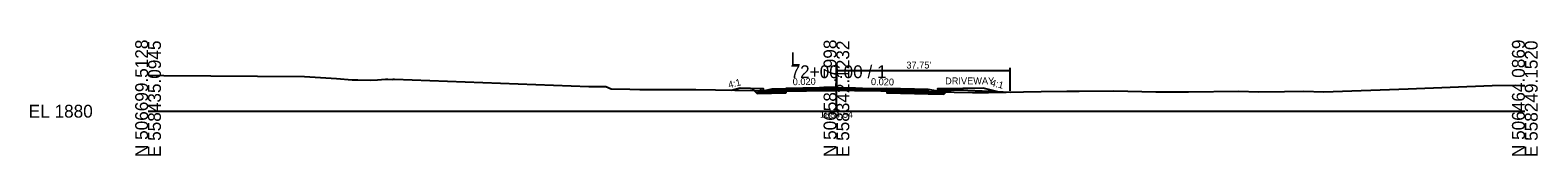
# Model space of a CAD drawing. Extents: x -26 to 4603, y -10 to 4703.
# Drawn here: x 2974.3 to 3302.8, y 835.3 to 860.4 of the extents above; entities that cross this region are included whole.
import ezdxf

# ---------------------------------------------------------------- set-up
doc = ezdxf.new("R2010")
doc.units = 0
for name, color, linetype in [('Default', 7, 'Continuous'), ('Exist Cross Section Cell', 7, 'Continuous'), ('Exist XS Ground Line', 7, 'Continuous'), ('Prop CMT Pvmt Course 1', 7, 'Continuous'), ('Prop CMT Pvmt Course 2', 7, 'Continuous'), ('Prop CMT Pvmt Course 3', 7, 'Continuous'), ('Prop CMT Pvmt Milling', 7, 'Continuous'), ('Prop CMT Shear Line', 7, 'Continuous'), ('Prop CMT Shld Paved Course 2', 7, 'Continuous'), ('Prop CMT Shld Paved Course 3', 7, 'Continuous'), ('Prop CMT Subgrade Earthwork', 7, 'Continuous'), ('Prop Conc Curb and Gutter', 7, 'Continuous'), ('Prop Corridor Mesh Bottom', 7, 'Continuous'), ('Prop XS Finish Grade', 7, 'Continuous'), ('Prop XS Label Text', 7, 'Continuous'), ('Prop XS SS Elevation Text', 7, 'Continuous'), ('Scratch_Level_0', 7, 'Continuous'), ('Scratch_Level_9', 7, 'Continuous')]:
    doc.layers.add(name, color=color, linetype=linetype)

msp = doc.modelspace()

# ---------------------------------------------------------------- linework, layer by layer
at = {"layer": 'Exist Cross Section Cell'}
for p, q in [((3150, 845), (3150, 855)), ((3000, 845), (3150, 845)), ((3150, 845), (3300, 845))]:
    msp.add_line(p, q, dxfattribs=at)
at = {"layer": 'Exist XS Ground Line'}
msp.add_lwpolyline([(3000, 852.83), (3003.45, 852.8), (3034.12, 852.55), (3041.03, 852.13), (3044.44, 851.81), (3045.7, 851.85), (3048.37, 851.75), (3049.97, 851.84), (3051.76, 851.95), (3052.24, 851.98), (3053.37, 851.9), (3053.42, 852), (3053.67, 851.99), (3096.07, 850.41), (3097.97, 850.38), (3099.73, 850.36), (3100.94, 849.86), (3104.97, 849.81), (3107.13, 849.75), (3113.36, 849.74), (3119.39, 849.76), (3132.18, 849.5), (3133.44, 849.47), (3134.15, 849.46), (3152.76, 849.55), (3153.2, 849.55), (3153.95, 849.54), (3154.03, 849.53), (3154.15, 849.53), (3155.68, 849.51), (3179.67, 849.07), (3183.14, 849.05), (3194.59, 849.27), (3200.24, 849.36), (3202.91, 849.37), (3210.41, 849.47), (3219.59, 849.23), (3226.74, 849.23), (3237.66, 849.34), (3241.98, 849.25), (3247.65, 849.3), (3251.77, 849.33), (3256.23, 849.24), (3274.58, 849.91), (3292.9, 850.61), (3298.03, 850.66), (3300, 850.56)], dxfattribs=at)
at = {"layer": 'Prop CMT Pvmt Course 1'}
for points in [[(3136, 849.87), (3139, 849.93), (3139, 849.68), (3139, 849.68), (3136, 849.62), (3136, 849.62), (3136, 849.62), (3136, 849.87), (3136, 849.87)], [(3139, 849.93), (3139, 849.48), (3139, 849.48), (3139, 849.48), (3150, 849.54), (3150, 849.54), (3150, 850.15), (3139, 849.93), (3139, 849.93)], [(3161, 849.93), (3161, 849.93), (3161, 849.41), (3161, 849.41), (3161, 849.41), (3155.68, 849.51), (3155.68, 849.51), (3154.15, 849.53), (3154.03, 849.53), (3153.95, 849.54), (3153.2, 849.55), (3152.76, 849.55), (3152.76, 849.55), (3150, 849.54), (3150, 849.54), (3150, 850.15), (3152.76, 850.1), (3152.76, 850.1), (3153.2, 850.09), (3153.95, 850.07), (3154.03, 850.07), (3154.15, 850.07), (3155.68, 850.04), (3155.68, 850.04), (3161, 849.93)], [(3170, 849.75), (3161, 849.93), (3161, 849.68), (3161, 849.68), (3170, 849.5), (3170, 849.5), (3170, 849.5), (3170, 849.75), (3170, 849.75)]]:
    msp.add_lwpolyline(points, dxfattribs=at)
at = {"layer": 'Prop CMT Pvmt Course 2'}
for points in [[(3136, 849.62), (3139, 849.68), (3139, 849.35), (3139, 849.35), (3136, 849.29), (3136, 849.29), (3136, 849.29), (3136, 849.62), (3136, 849.62)], [(3170, 849.5), (3161, 849.68), (3161, 849.35), (3161, 849.35), (3170, 849.17), (3170, 849.17), (3170, 849.17), (3170, 849.5), (3170, 849.5)]]:
    msp.add_lwpolyline(points, dxfattribs=at)
at = {"layer": 'Prop CMT Pvmt Course 3'}
for points in [[(3136, 849.29), (3139, 849.35), (3139, 848.97), (3139, 848.97), (3136, 848.91), (3136, 848.91), (3136, 848.91), (3136, 849.29), (3136, 849.29)], [(3170, 849.17), (3161, 849.35), (3161, 848.97), (3161, 848.97), (3170, 848.79), (3170, 848.79), (3170, 848.79), (3170, 849.17), (3170, 849.17)], [(3173, 849.11), (3170, 849.17), (3170, 848.79), (3170, 848.79), (3173.38, 848.73), (3173.38, 848.73), (3173.38, 848.73), (3173, 849.11), (3173, 849.11)]]:
    msp.add_lwpolyline(points, dxfattribs=at)
at = {"layer": 'Prop CMT Pvmt Milling'}
for points in [[(3139, 849.48), (3139, 849.48), (3150, 849.54)], [(3150, 849.54), (3152.76, 849.55), (3152.76, 849.55), (3153.2, 849.55), (3153.95, 849.54), (3154.03, 849.53), (3154.15, 849.53), (3155.68, 849.51), (3155.68, 849.51), (3161, 849.41), (3161, 849.41)]]:
    msp.add_lwpolyline(points, dxfattribs=at)
at = {"layer": 'Prop CMT Shld Paved Course 2'}
for points in [[(3139, 849.68), (3139, 849.35), (3139, 849.35), (3147.96, 849.53), (3147.96, 849.53), (3150, 849.54), (3150, 849.54), (3150, 849.9), (3139, 849.68), (3139, 849.68)], [(3161, 849.68), (3161, 849.68), (3161, 849.35), (3161, 849.35), (3161, 849.35), (3155.68, 849.45), (3155.68, 849.45), (3154.15, 849.48), (3154.03, 849.49), (3153.95, 849.49), (3153.2, 849.5), (3152.76, 849.51), (3151.25, 849.54), (3151.25, 849.54), (3150, 849.54), (3150, 849.54), (3150, 849.9), (3152.76, 849.85), (3152.76, 849.85), (3153.2, 849.84), (3153.95, 849.82), (3154.03, 849.82), (3154.15, 849.82), (3155.68, 849.79), (3155.68, 849.79), (3161, 849.68)]]:
    msp.add_lwpolyline(points, dxfattribs=at)
at = {"layer": 'Prop CMT Shld Paved Course 3'}
msp.add_lwpolyline([(3133, 849.23), (3136, 849.29), (3136, 848.91), (3136, 848.91), (3132.7, 848.85), (3132.7, 848.85), (3132.7, 848.85), (3133, 849.23), (3133, 849.23)], dxfattribs=at)
at = {"layer": 'Prop CMT Subgrade Earthwork'}
for points in [[(3131.54, 850.01), (3132.7, 848.85), (3132.7, 848.85)], [(3132.7, 848.85), (3132.7, 848.85), (3139, 848.97)], [(3173.38, 848.73), (3173.38, 848.73), (3161, 848.97)], [(3174.4, 849.75), (3173.38, 848.73), (3173.38, 848.73)]]:
    msp.add_lwpolyline(points, dxfattribs=at)
at = {"layer": 'Prop Conc Curb and Gutter'}
for points in [[(3134, 849.47), (3136, 849.87), (3136, 849.29), (3136, 849.29), (3133.5, 849.24), (3133.5, 849.24), (3133.5, 849.24), (3133.5, 849.97), (3133.5, 849.97), (3134, 849.97), (3134, 849.47), (3134, 849.47), (3134, 849.47)], [(3172, 849.35), (3170, 849.75), (3170, 849.17), (3170, 849.17), (3172.5, 849.12), (3172.5, 849.12), (3172.5, 849.12), (3172.5, 849.85), (3172, 849.85), (3172, 849.85), (3172, 849.35), (3172, 849.35), (3172, 849.35)]]:
    msp.add_lwpolyline(points, dxfattribs=at)
at = {"layer": 'Prop Corridor Mesh Bottom'}
msp.add_lwpolyline([(3170, 849.75), (3170, 849.5)], dxfattribs=at)
at = {"layer": 'Prop XS Finish Grade'}
for p, q in [((3129, 850.06), (3133.5, 849.97)), ((3172.5, 849.85), (3187.85, 849.12))]:
    msp.add_line(p, q, dxfattribs=at)
for points in [[(3127.16, 849.6), (3129, 850.06), (3129, 850.06)], [(3133.5, 849.97), (3133.49, 849.97)]]:
    msp.add_lwpolyline(points, dxfattribs=at)
at = {"layer": 'Prop XS Label Text'}
for p, q in [((3150, 854.6), (3150, 850.71)), ((3187.76, 854.46), (3187.76, 849.44)), ((3187.76, 853.81), (3150, 853.81))]:
    msp.add_line(p, q, dxfattribs=at)
at = {"layer": 'Scratch_Level_0'}
for points in [[(3172.51, 849.85), (3172.51, 849.85), (3172.5, 849.52), (3172.5, 849.52), (3172.5, 849.52), (3177.52, 849.62), (3177.52, 849.62), (3177.51, 849.95), (3172.51, 849.85)], [(3172.5, 849.85), (3172.51, 849.85)], [(3182, 850.04), (3177.51, 849.95), (3177.51, 849.95)], [(3185.75, 849.1), (3182, 850.04), (3182, 850.04)]]:
    msp.add_lwpolyline(points, dxfattribs=at)
at = {"layer": 'Scratch_Level_9'}
msp.add_lwpolyline([(3136, 849.87), (3136, 849.62)], dxfattribs=at)

# ---------------------------------------------------------------- texts
at = {"layer": 'Default'}
msp.add_text('-', height=0.0001, dxfattribs=at).set_placement((3000, 845))
at = {"layer": 'Exist Cross Section Cell'}
for s, p in [('N 506699.5128', (3000, 835)), ('E 558435.0945', (3002.8, 835)), ('N 506581.7998', (3150, 835)), ('E 558342.1232', (3152.8, 835)), ('N 506464.0869', (3300, 835)), ('E 558249.1520', (3302.8, 835))]:
    msp.add_text(s, height=2.8, rotation=90, dxfattribs=at).set_placement(p)
for s, p in [('L', (3140, 855)), ('72+00.00 / 1', (3140, 852.2)), ('EL 1880', (2974, 843.6))]:
    msp.add_text(s, height=2.8, dxfattribs=at).set_placement(p)
at = {"layer": 'Prop CMT Shear Line'}
for p in [(3127.18, 849.6), (3129, 850.06), (3133.49, 849.97), (3134, 849.47), (3136, 849.87), (3136, 849.87), (3150, 850.15), (3170, 849.75), (3170, 849.75), (3172, 849.35), (3185.75, 849.1)]:
    msp.add_text('X', height=0.0025, dxfattribs=at).set_placement(p)
at = {"layer": 'Prop XS Label Text'}
for s, rotation, p in [("37.75'", 0.0969, (3165.24, 854.3)), ('4:1', 14.0362, (3126.61, 849.98)), ('0.020', 1.1458, (3140.48, 850.66)), ('0.020', 358.8542, (3157.51, 850.7)), ('DRIVEWAY', 0.0969, (3173.68, 850.85))]:
    msp.add_text(s, height=1.5, rotation=rotation, dxfattribs=at).set_placement(p)
at = {"layer": 'Prop XS SS Elevation Text'}
msp.add_text('1884.54', height=1.5, dxfattribs=at).set_placement((3146.38, 843.56))
at = {"layer": 'Scratch_Level_0'}
msp.add_text('4:1', height=1.5, rotation=345.9638, dxfattribs=at).set_placement((3183.51, 850.55))
for p in [(3172.51, 849.85), (3177.51, 849.95), (3182, 850.04)]:
    msp.add_text('X', height=0.0025, dxfattribs=at).set_placement(p)

doc.saveas('drawing.dxf')
